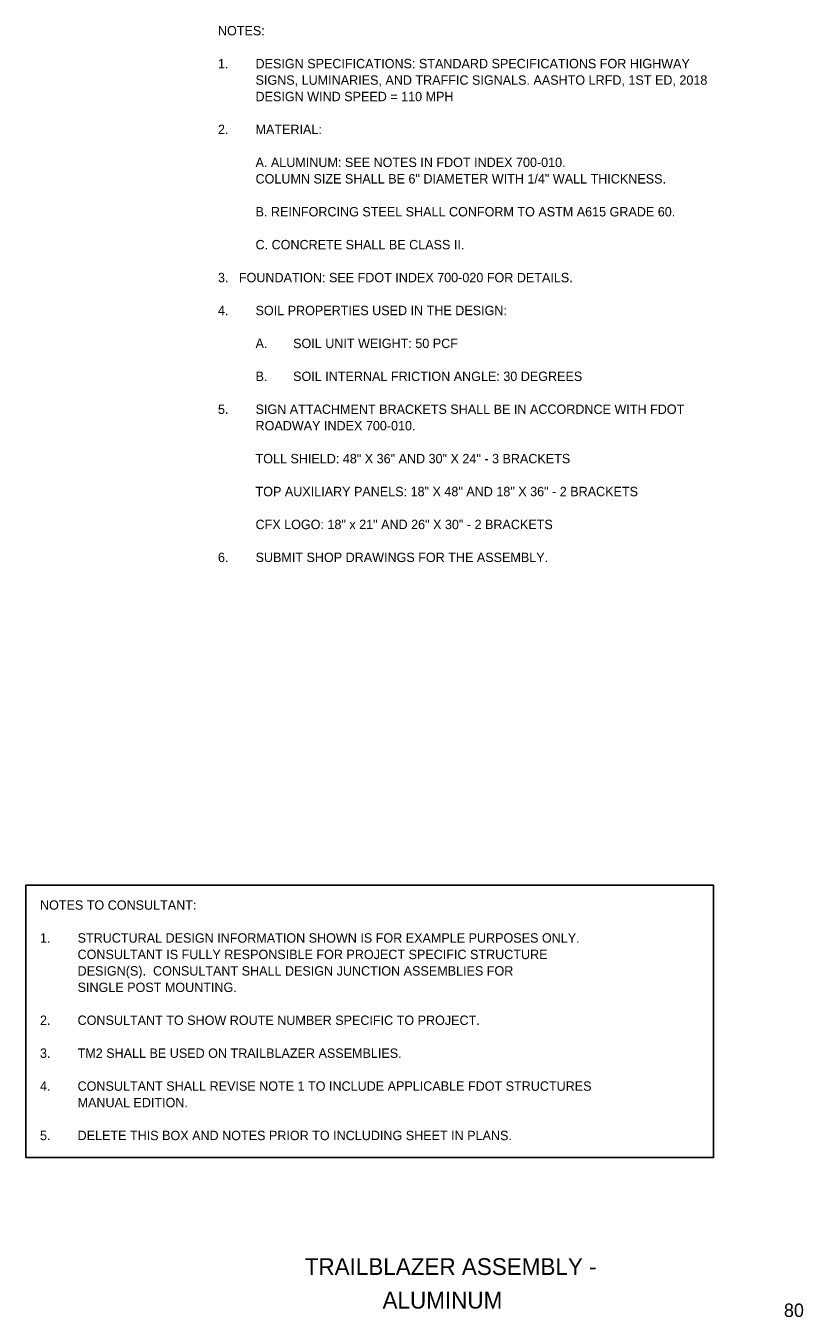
# Model space of a CAD drawing. Extents: x 52649 to 53276, y 9410 to 9805.
# Drawn here: x 53044.7 to 53276.3, y 9420.2 to 9804.6 of the extents above; entities that cross this region are included whole.
import ezdxf

# ---------------------------------------------------------------- set-up
doc = ezdxf.new("R2010")
doc.units = 0
for name, color, linetype in [('TextAlert', 7, 'Continuous'), ('TextMisc', 7, 'Continuous'), ('TextNotes', 7, 'Continuous'), ('TextShtNo', 7, 'Continuous')]:
    doc.layers.add(name, color=color, linetype=linetype)

msp = doc.modelspace()

# ---------------------------------------------------------------- linework, layer by layer
at = {"layer": 'TextAlert'}
msp.add_lwpolyline([(53044.7, 9467.65), (53249.61, 9467.65), (53249.61, 9548.74), (53044.7, 9548.74)], close=True, dxfattribs=at)

# ---------------------------------------------------------------- texts
for s, p in [('NOTES TO CONSULTANT:', (53048.93, 9541.45)), ('1.', (53048.93, 9531.65)), ('STRUCTURAL DESIGN INFORMATION SHOWN IS FOR EXAMPLE PURPOSES ONLY.', (53060.13, 9531.65)), ('CONSULTANT IS FULLY RESPONSIBLE FOR PROJECT SPECIFIC STRUCTURE', (53060.13, 9526.75)), ('DESIGN(S).  CONSULTANT SHALL DESIGN JUNCTION ASSEMBLIES FOR', (53060.13, 9521.85)), ('SINGLE POST MOUNTING.', (53060.13, 9516.95)), ('2.', (53048.93, 9507.15)), ('CONSULTANT TO SHOW ROUTE NUMBER SPECIFIC TO PROJECT.', (53060.13, 9507.15)), ('3.', (53048.93, 9497.35)), ('TM2 SHALL BE USED ON TRAILBLAZER ASSEMBLIES.', (53060.13, 9497.35)), ('4.', (53048.93, 9487.55)), ('CONSULTANT SHALL REVISE NOTE 1 TO INCLUDE APPLICABLE FDOT STRUCTURES', (53060.13, 9487.55)), ('MANUAL EDITION.', (53060.13, 9482.65)), ('5.', (53048.93, 9472.85)), ('DELETE THIS BOX AND NOTES PRIOR TO INCLUDING SHEET IN PLANS.', (53060.13, 9472.85))]:
    msp.add_text(s, height=2.8, dxfattribs=at).set_placement(p)
at = {"layer": 'TextMisc'}
for s, p in [(' TRAILBLAZER ASSEMBLY - ', (53125.95, 9432.71)), ('        ALUMINUM        ', (53136.14, 9422.71))]:
    msp.add_text(s, height=5, rotation=360, dxfattribs=at).set_placement(p)
at = {"layer": 'TextNotes'}
for s, p in [('NOTES:', (53101.95, 9801.76)), ('1.', (53101.95, 9791.96)), ('DESIGN SPECIFICATIONS: STANDARD SPECIFICATIONS FOR HIGHWAY', (53113.15, 9791.96)), ('SIGNS, LUMINARIES, AND TRAFFIC SIGNALS. AASHTO LRFD, 1ST ED, 2018', (53113.15, 9787.06)), ('DESIGN WIND SPEED = 110 MPH', (53113.15, 9782.16)), ('2.', (53101.95, 9772.36)), ('MATERIAL:', (53113.15, 9772.36)), ('A. ALUMINUM: SEE NOTES IN FDOT INDEX 700-010. ', (53113.15, 9762.56)), ('COLUMN SIZE SHALL BE 6" DIAMETER WITH 1/4" WALL THICKNESS.', (53113.15, 9757.66)), ('B. REINFORCING STEEL SHALL CONFORM TO ASTM A615 GRADE 60.', (53113.15, 9747.86)), ('C. CONCRETE SHALL BE CLASS II.', (53113.15, 9738.06)), ('3.   FOUNDATION: SEE FDOT INDEX 700-020 FOR DETAILS.', (53101.95, 9728.26)), ('4.', (53101.95, 9718.46)), ('SOIL PROPERTIES USED IN THE DESIGN:  ', (53113.15, 9718.46)), ('A.', (53113.15, 9708.66)), ('SOIL UNIT WEIGHT: 50 PCF', (53124.35, 9708.66)), ('B.', (53113.15, 9698.86)), ('SOIL INTERNAL FRICTION ANGLE: 30 DEGREES', (53124.35, 9698.86)), ('5. ', (53101.95, 9689.06)), ('SIGN ATTACHMENT BRACKETS SHALL BE IN ACCORDNCE WITH FDOT', (53113.15, 9689.06)), ('ROADWAY INDEX 700-010.', (53113.15, 9684.16)), ('TOLL SHIELD: 48" X 36" AND 30" X 24" - 3 BRACKETS', (53113.15, 9674.36)), ('TOP AUXILIARY PANELS: 18" X 48" AND 18" X 36" - 2 BRACKETS', (53113.15, 9664.56)), ('CFX LOGO: 18" x 21" AND 26" X 30" - 2 BRACKETS ', (53113.15, 9654.76)), ('6.', (53101.95, 9644.96)), ('SUBMIT SHOP DRAWINGS FOR THE ASSEMBLY.', (53113.15, 9644.96))]:
    msp.add_text(s, height=2.8, dxfattribs=at).set_placement(p)
at = {"layer": 'TextShtNo'}
msp.add_text('80', height=4, rotation=360, dxfattribs=at).set_placement((53270.58, 9420.21))

doc.saveas('drawing.dxf')
